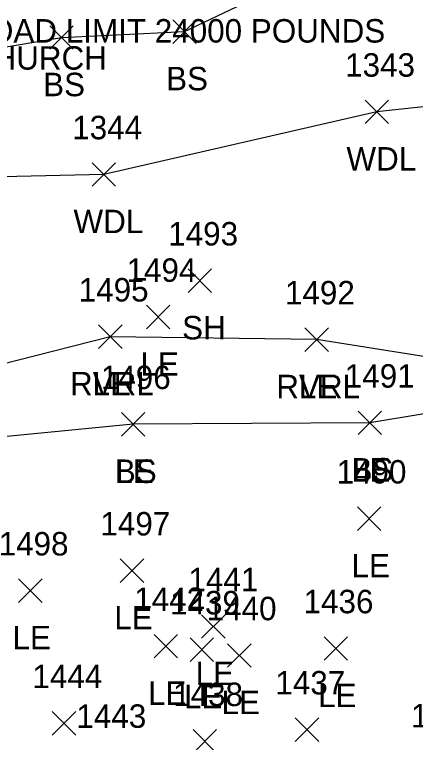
# Model space of a CAD drawing. Extents: x 1620157 to 1620595, y 115111 to 117885.
# Drawn here: x 1620358.1 to 1620392.2, y 115415.3 to 115477.3 of the extents above; entities that cross this region are included whole.
import ezdxf

# ---------------------------------------------------------------- set-up
doc = ezdxf.new("R2010")
doc.units = 0
for name, color, linetype in [('L_A', 7, 'Continuous'), ('L_I', 7, 'Continuous'), ('L_TIC', 7, 'Continuous'), ('LAWA', 7, 'Continuous'), ('LAWE', 7, 'Continuous'), ('LELB', 7, 'Continuous'), ('S_C', 7, 'Continuous')]:
    doc.layers.add(name, color=color, linetype=linetype)

msp = doc.modelspace()

# ---------------------------------------------------------------- linework, layer by layer
at = {"layer": 'L_TIC'}
for points in [[(1620371.56, 115474.834), (1620373.56, 115476.834)], [(1620373.56, 115474.834), (1620371.56, 115476.834)], [(1620361.089, 115474.331), (1620363.089, 115476.331)], [(1620363.089, 115474.331), (1620361.089, 115476.331)], [(1620387.936, 115467.996), (1620389.936, 115469.996)], [(1620389.936, 115467.996), (1620387.936, 115469.996)], [(1620364.7, 115462.66), (1620366.7, 115464.66)], [(1620366.7, 115462.66), (1620364.7, 115464.66)], [(1620372.873, 115453.608), (1620374.873, 115455.608)], [(1620374.873, 115453.608), (1620372.873, 115455.608)], [(1620369.325, 115450.51), (1620371.325, 115452.51)], [(1620371.325, 115450.51), (1620369.325, 115452.51)], [(1620365.252, 115448.835), (1620367.252, 115450.835)], [(1620367.252, 115448.835), (1620365.252, 115450.835)], [(1620365.252, 115448.835), (1620367.252, 115450.835)], [(1620367.252, 115448.835), (1620365.252, 115450.835)], [(1620382.813, 115448.588), (1620384.813, 115450.588)], [(1620384.813, 115448.588), (1620382.813, 115450.588)], [(1620382.813, 115448.588), (1620384.813, 115450.588)], [(1620384.813, 115448.588), (1620382.813, 115450.588)], [(1620367.19, 115441.372), (1620369.19, 115443.372)], [(1620369.19, 115441.372), (1620367.19, 115443.372)], [(1620367.19, 115441.372), (1620369.19, 115443.372)], [(1620369.19, 115441.372), (1620367.19, 115443.372)], [(1620387.34, 115441.493), (1620389.34, 115443.493)], [(1620389.34, 115441.493), (1620387.34, 115443.493)], [(1620387.34, 115441.493), (1620389.34, 115443.493)], [(1620389.34, 115441.493), (1620387.34, 115443.493)], [(1620387.294, 115433.323), (1620389.294, 115435.323)], [(1620389.294, 115433.323), (1620387.294, 115435.323)], [(1620367.099, 115428.894), (1620369.099, 115430.894)], [(1620369.099, 115428.894), (1620367.099, 115430.894)], [(1620358.436, 115427.189), (1620360.436, 115429.189)], [(1620360.436, 115427.189), (1620358.436, 115429.189)], [(1620374.027, 115424.139), (1620376.027, 115426.139)], [(1620376.027, 115424.139), (1620374.027, 115426.139)], [(1620369.976, 115422.458), (1620371.976, 115424.458)], [(1620371.976, 115422.458), (1620369.976, 115424.458)], [(1620373.036, 115422.167), (1620375.036, 115424.167)], [(1620375.036, 115422.167), (1620373.036, 115424.167)], [(1620384.452, 115422.265), (1620386.452, 115424.265)], [(1620386.452, 115422.265), (1620384.452, 115424.265)], [(1620376.233, 115421.67), (1620378.233, 115423.67)], [(1620378.233, 115421.67), (1620376.233, 115423.67)], [(1620361.312, 115415.89), (1620363.312, 115417.89)], [(1620363.312, 115415.89), (1620361.312, 115417.89)], [(1620381.996, 115415.344), (1620383.996, 115417.344)], [(1620383.996, 115415.344), (1620381.996, 115417.344)], [(1620373.291, 115414.353), (1620375.291, 115416.353)], [(1620375.291, 115414.353), (1620373.291, 115416.353)]]:
    msp.add_lwpolyline(points, dxfattribs=at)
at = {"layer": 'LAWA'}
msp.add_lwpolyline([(1620457.22, 115455.235), (1620436.741, 115469.876), (1620415.841, 115471.908), (1620388.936, 115468.996), (1620365.7, 115463.66), (1620354.532, 115463.399)], dxfattribs=at)
at = {"layer": 'LAWE'}
msp.add_lwpolyline([(1620445.954, 115439.559), (1620430.826, 115447.795), (1620415.576, 115450.852), (1620397.572, 115447.406), (1620383.813, 115449.588), (1620366.252, 115449.835), (1620353.621, 115446.61), (1620348.794, 115438.684), (1620343.851, 115441.035)], dxfattribs=at)
at = {"layer": 'LELB'}
for points in [[(1620353.276, 115465.348), (1620354.004, 115473.97), (1620362.089, 115475.331), (1620372.56, 115475.834), (1620392.598, 115485.393), (1620443.084, 115483.249)], [(1620445.933, 115434.696), (1620432.19, 115440.311), (1620415.154, 115443.989), (1620397.761, 115444.055), (1620388.34, 115442.493), (1620368.19, 115442.372), (1620354.516, 115441.049), (1620350.878, 115433.955), (1620346.485, 115432.501), (1620338.973, 115434.365), (1620325.326, 115430.427), (1620316.032, 115427.322), (1620308.723, 115416.914), (1620294.485, 115412.65), (1620281.316, 115408.44), (1620263.956, 115399.244), (1620237.914, 115391.699), (1620225.014, 115391.235), (1620212.858, 115385.97)]]:
    msp.add_lwpolyline(points, dxfattribs=at)

# ---------------------------------------------------------------- texts
at = {"layer": 'L_A'}
for s, p in [('BS', (1620371.001, 115470.834)), ('BS', (1620360.53, 115470.331)), ('WDL', (1620386.353, 115463.996)), ('WDL', (1620363.117, 115458.66)), ('SH', (1620372.362, 115449.608)), ('LE', (1620368.814, 115446.51)), ('RVRL', (1620362.819, 115444.835)), ('LE', (1620364.74, 115444.835)), ('RVRL', (1620380.38, 115444.588)), ('LE', (1620382.301, 115444.588)), ('BS', (1620366.631, 115437.372)), ('LE', (1620366.678, 115437.372)), ('BS', (1620386.781, 115437.493)), ('LE', (1620386.828, 115437.493)), ('LE', (1620386.782, 115429.323)), ('LE', (1620366.587, 115424.894)), ('LE', (1620357.924, 115423.189)), ('LE', (1620373.515, 115420.139)), ('LE', (1620369.464, 115418.458)), ('LE', (1620372.524, 115418.167)), ('LE', (1620383.94, 115418.265)), ('LE', (1620375.721, 115417.67))]:
    msp.add_text(s, height=2, dxfattribs=at).set_placement(p)
at = {"layer": 'L_I'}
for s, p in [('1343', (1620386.243, 115471.996)), ('1344', (1620363.007, 115466.66)), ('1493', (1620371.181, 115457.608)), ('1494', (1620367.633, 115454.51)), ('1495', (1620363.559, 115452.835)), ('1495', (1620363.559, 115452.835)), ('1492', (1620381.12, 115452.588)), ('1492', (1620381.12, 115452.588)), ('1496', (1620365.442, 115445.372)), ('1496', (1620365.442, 115445.372)), ('1491', (1620386.214, 115445.493)), ('1491', (1620386.214, 115445.493)), ('1490', (1620385.515, 115437.323)), ('1497', (1620365.406, 115432.894)), ('1498', (1620356.743, 115431.189)), ('1441', (1620372.901, 115428.139)), ('1442', (1620368.283, 115426.458)), ('1439', (1620371.336, 115426.167)), ('1436', (1620382.704, 115426.265)), ('1440', (1620374.454, 115425.67)), ('1444', (1620359.619, 115419.89)), ('1437', (1620380.303, 115419.344)), ('1438', (1620371.598, 115418.353)), ('1443', (1620363.362, 115416.501)), ('1419', (1620391.851, 115416.537))]:
    msp.add_text(s, height=2, dxfattribs=at).set_placement(p)
at = {"layer": 'S_C'}
for s, p in [('LEGAL LOAD LIMIT 24000 POUNDS', (1620345.066, 115474.903)), ('GUILFORD COMMUNITY CHURCH', (1620322.578, 115472.594))]:
    msp.add_text(s, height=2, dxfattribs=at).set_placement(p)

doc.saveas('drawing.dxf')
